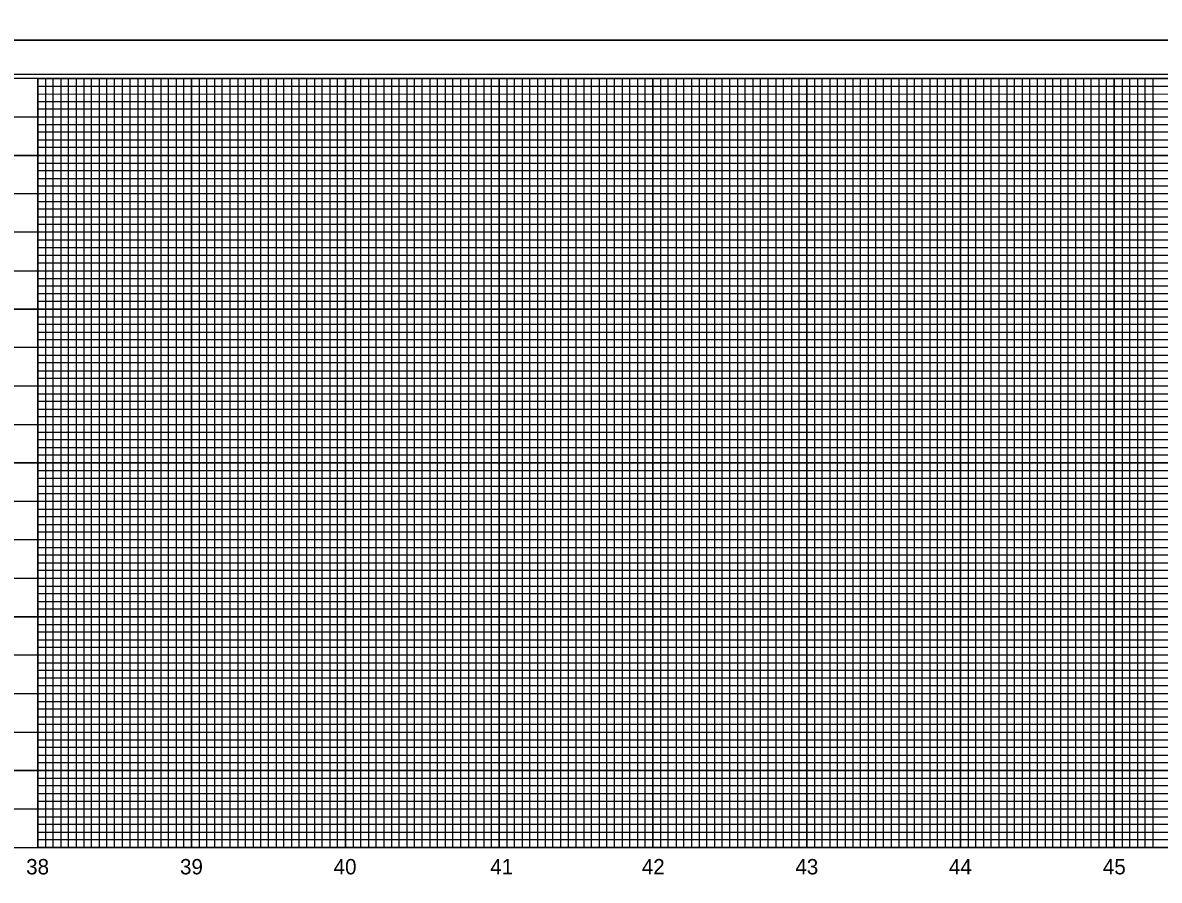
# Model space of a CAD drawing. Extents: x 1754992 to 1757273, y 732111 to 735411.
# Drawn here: x 1755388 to 1756127, y 733764 to 734322 of the extents above; entities that cross this region are included whole.
import ezdxf

# ---------------------------------------------------------------- set-up
doc = ezdxf.new("R2010")
doc.units = 0
for name, color, linetype in [('Scratch_Level_3', 7, 'Continuous'), ('Sheet Cutting Line CELL', 7, 'Continuous'), ('Sheet DOT Grid CELL', 7, 'Continuous'), ('Sheet Plot Border Inside CELL', 7, 'Continuous'), ('Sheet Plot Border Outside CELL', 7, 'Continuous'), ('Sheet Profile CELL', 7, 'Continuous'), ('Sheet Profile Grid Major CELL', 7, 'Continuous'), ('Sheet Profile Grid Middle CELL', 7, 'Continuous'), ('Sheet Profile Grid Minor CELL', 7, 'Continuous')]:
    doc.layers.add(name, color=color, linetype=linetype)

msp = doc.modelspace()

# ---------------------------------------------------------------- linework, layer by layer
at = {"layer": 'Scratch_Level_3'}
msp.add_lwpolyline([(1755397.67, 733785.78), (1755397.67, 734285.78), (1756647.62, 734285.78), (1756647.63, 734052.66), (1756647.67, 733785.78)], close=True, dxfattribs=at)
at = {"layer": 'Sheet Cutting Line CELL'}
for p, q in [((1755180.67, 734310.78), (1756864.67, 734310.78)), ((1756864.67, 734310.78), (1755180.67, 734310.78))]:
    msp.add_line(p, q, dxfattribs=at)
at = {"layer": 'Sheet DOT Grid CELL'}
for p, q in [((1755397.67, 733785.78), (1755397.67, 734285.78)), ((1755447.67, 733785.78), (1755447.67, 734285.78)), ((1755497.67, 733785.78), (1755497.67, 734285.78)), ((1755547.67, 733785.78), (1755547.67, 734285.78)), ((1755597.67, 733785.78), (1755597.67, 734285.78)), ((1755647.67, 733785.78), (1755647.67, 734285.78)), ((1755697.67, 733785.78), (1755697.67, 734285.78)), ((1755747.67, 733785.78), (1755747.67, 734285.78)), ((1755797.67, 733785.78), (1755797.67, 734285.78)), ((1755847.67, 733785.78), (1755847.67, 734285.78)), ((1755897.67, 733785.78), (1755897.67, 734285.78)), ((1755947.67, 733785.78), (1755947.67, 734285.78)), ((1755997.67, 733785.78), (1755997.67, 734285.78)), ((1756047.67, 733785.78), (1756047.67, 734285.78)), ((1756097.67, 733785.78), (1756097.67, 734285.78)), ((1756647.62, 734235.78), (1755347.67, 734235.78)), ((1756647.62, 734185.78), (1755347.67, 734185.78)), ((1756647.67, 734135.78), (1755347.67, 734135.78)), ((1756647.63, 734085.78), (1755347.67, 734085.78)), ((1756847.67, 734035.78), (1755347.67, 734035.78)), ((1756847.67, 733985.78), (1755347.67, 733985.78)), ((1756847.67, 733935.78), (1755347.67, 733935.78)), ((1756847.67, 733885.78), (1755347.67, 733885.78)), ((1756847.67, 733835.78), (1755347.67, 733835.78))]:
    msp.add_line(p, q, dxfattribs=at)
at = {"layer": 'Sheet Plot Border Inside CELL'}
msp.add_lwpolyline([(1755193.67, 733233.23), (1756860.17, 733233.23), (1756860.17, 734288.33), (1755193.67, 734288.33)], close=True, dxfattribs=at)
at = {"layer": 'Sheet Plot Border Outside CELL'}
for points in [[(1755180.67, 734310.78), (1756864.67, 734310.78), (1756864.67, 735410.78), (1755180.67, 735410.78)], [(1755180.67, 733210.78), (1756864.67, 733210.78), (1756864.67, 734310.78), (1755180.67, 734310.78)]]:
    msp.add_lwpolyline(points, close=True, dxfattribs=at)
at = {"layer": 'Sheet Profile CELL'}
msp.add_line((1755347.67, 733785.78), (1756847.67, 733785.78), dxfattribs=at)
msp.add_lwpolyline([(1756847.67, 734285.78), (1755347.67, 734285.78), (1755347.67, 733235.78), (1756847.67, 733235.78)], close=True, dxfattribs=at)
at = {"layer": 'Sheet Profile Grid Major CELL'}
for points in [[(1755397.67, 734285.78), (1755397.67, 733785.78), (1755447.67, 733785.78), (1755447.67, 734285.78), (1755497.67, 734285.78), (1755497.67, 733785.78), (1755547.67, 733785.78), (1755547.67, 734285.78), (1755597.67, 734285.78), (1755597.67, 733785.78), (1755647.67, 733785.78), (1755647.67, 734285.78), (1755697.67, 734285.78), (1755697.67, 733785.78), (1755747.67, 733785.78), (1755747.67, 734285.78), (1755797.67, 734285.78), (1755797.67, 733785.78), (1755847.67, 733785.78), (1755847.67, 734285.78), (1755897.67, 734285.78), (1755897.67, 733785.78), (1755947.67, 733785.78), (1755947.67, 734285.78), (1755997.67, 734285.78), (1755997.67, 733785.78), (1756047.67, 733785.78), (1756047.67, 734285.78), (1756097.67, 734285.78), (1756097.67, 733785.78), (1756147.67, 733785.78)], [(1755347.67, 734235.78), (1756647.67, 734235.78)], [(1756647.67, 734185.78), (1755347.67, 734185.78), (1755347.67, 734135.78), (1756647.67, 734135.78)], [(1756647.63, 734085.78), (1755347.67, 734085.78), (1755347.67, 734035.78), (1756847.67, 734035.78)], [(1756847.67, 733985.78), (1755347.67, 733985.78), (1755347.67, 733935.78), (1756847.67, 733935.78)], [(1756847.67, 733885.78), (1755347.67, 733885.78), (1755347.67, 733885.78), (1755347.67, 733835.78), (1756847.67, 733835.78)]]:
    msp.add_lwpolyline(points, dxfattribs=at)
at = {"layer": 'Sheet Profile Grid Middle CELL'}
msp.add_line((1755347.67, 734260.78), (1756647.62, 734260.78), dxfattribs=at)
for points in [[(1755422.67, 734285.78), (1755422.67, 733785.78), (1755472.67, 733785.78), (1755472.67, 734285.78), (1755522.67, 734285.78), (1755522.67, 733785.78), (1755572.67, 733785.78), (1755572.67, 734285.78), (1755622.67, 734285.78), (1755622.67, 733785.78), (1755672.67, 733785.78), (1755672.67, 734285.78), (1755722.67, 734285.78), (1755722.67, 733785.78), (1755772.67, 733785.78), (1755772.67, 734285.78), (1755822.67, 734285.78), (1755822.67, 733785.78), (1755872.67, 733785.78), (1755872.67, 734285.78), (1755922.67, 734285.78), (1755922.67, 733785.78), (1755972.67, 733785.78), (1755972.67, 733785.78), (1755972.67, 734285.78), (1756022.67, 734285.78), (1756022.67, 733785.78), (1756072.67, 733785.78), (1756072.67, 734285.78), (1756122.67, 734285.78), (1756122.67, 733785.78), (1756172.67, 733785.78)], [(1756647.67, 734210.78), (1755347.67, 734210.78), (1755347.67, 734160.78), (1756647.67, 734160.78)], [(1756647.62, 734110.78), (1755347.67, 734110.78), (1755347.67, 734060.78), (1756647.63, 734060.78)], [(1756847.67, 734010.78), (1755347.67, 734010.78), (1755347.67, 733960.78), (1756847.67, 733960.78)], [(1756847.67, 733910.78), (1755347.67, 733910.78), (1755347.67, 733860.78), (1756847.67, 733860.78)], [(1756847.67, 733810.78), (1755347.67, 733810.78)]]:
    msp.add_lwpolyline(points, dxfattribs=at)
at = {"layer": 'Sheet Profile Grid Minor CELL'}
for p, q in [((1755397.67, 734280.78), (1756647.67, 734280.78)), ((1755397.67, 734275.78), (1755397.67, 734275.78)), ((1756647.67, 734275.78), (1755397.67, 734275.43)), ((1755397.67, 734270.78), (1756647.67, 734270.78)), ((1756647.62, 734150.78), (1755397.67, 734150.78)), ((1756647.67, 734145.78), (1755397.67, 734145.78)), ((1756647.67, 734140.78), (1755397.67, 734140.78)), ((1755397.67, 734130.78), (1756647.67, 734130.78)), ((1756647.67, 734125.78), (1755397.67, 734125.78)), ((1755397.67, 734120.78), (1756647.62, 734120.78)), ((1756647.62, 734100.78), (1755397.67, 734100.78)), ((1755397.67, 734095.78), (1756647.62, 734095.78)), ((1756647.63, 734075.78), (1755397.67, 734075.78)), ((1755397.67, 734070.78), (1756647.63, 734070.78)), ((1756797.67, 734050.78), (1755397.67, 734050.78)), ((1755397.67, 734045.78), (1756797.67, 734045.78)), ((1756797.67, 734040.78), (1755397.67, 734040.78)), ((1755397.67, 734030.78), (1756797.67, 734030.78)), ((1756797.67, 734025.78), (1755397.67, 734025.78)), ((1755397.67, 734020.78), (1756797.67, 734020.78)), ((1756797.67, 734015.78), (1755397.67, 734015.78)), ((1755397.67, 734005.78), (1756797.67, 734005.78)), ((1756797.67, 734000.78), (1755397.67, 734000.78)), ((1755397.67, 733995.78), (1756797.67, 733995.78)), ((1756797.67, 733990.78), (1755397.67, 733990.78)), ((1755397.67, 733980.78), (1756797.67, 733980.78)), ((1756797.67, 733975.78), (1755397.67, 733975.78)), ((1755397.67, 733970.78), (1756797.67, 733970.78)), ((1756797.67, 733965.78), (1755397.67, 733965.78)), ((1755397.67, 733955.78), (1756797.67, 733955.78)), ((1756797.67, 733950.78), (1755397.67, 733950.78)), ((1755397.67, 733945.78), (1756797.67, 733945.78)), ((1756797.67, 733940.78), (1755397.67, 733940.78)), ((1755397.67, 733930.78), (1756797.67, 733930.78)), ((1756797.67, 733925.78), (1755397.67, 733925.78)), ((1755397.67, 733920.78), (1756797.67, 733920.78)), ((1756797.67, 733915.78), (1755397.67, 733915.78)), ((1755397.67, 733905.78), (1756797.67, 733905.78)), ((1756797.67, 733900.78), (1755397.67, 733900.78)), ((1756797.67, 733895.78), (1755397.67, 733895.78)), ((1756797.67, 733890.78), (1755397.67, 733890.78)), ((1755397.67, 733880.78), (1756797.67, 733880.78)), ((1756797.67, 733875.78), (1755397.67, 733875.78)), ((1755397.67, 733870.78), (1756797.67, 733870.78)), ((1756797.67, 733865.78), (1755397.67, 733865.78)), ((1755397.67, 733855.78), (1756797.67, 733855.78)), ((1756797.67, 733850.78), (1755397.67, 733850.78)), ((1755397.67, 733845.78), (1756797.67, 733845.78)), ((1756797.67, 733840.78), (1755397.67, 733840.78)), ((1755397.67, 733830.78), (1756797.67, 733830.78)), ((1756797.67, 733825.78), (1755397.67, 733825.78)), ((1755397.67, 733820.78), (1756797.67, 733820.78)), ((1756797.67, 733815.78), (1755397.67, 733815.78)), ((1755397.67, 733805.78), (1756797.67, 733805.78)), ((1756797.67, 733800.78), (1755397.67, 733800.78)), ((1755397.67, 733795.78), (1756797.67, 733795.78))]:
    msp.add_line(p, q, dxfattribs=at)
for points in [[(1755402.67, 734285.78), (1755402.67, 733785.78), (1755407.67, 733785.78), (1755407.67, 734285.78), (1755412.67, 734285.78), (1755412.67, 733785.78), (1755417.67, 733785.78), (1755417.67, 734285.78), (1755427.67, 734285.78), (1755427.67, 733785.78), (1755432.67, 733785.78), (1755432.67, 734285.78), (1755437.67, 734285.78), (1755437.67, 733785.78), (1755442.67, 733785.78), (1755452.67, 733785.78), (1755457.67, 733785.78), (1755457.67, 734285.78), (1755462.67, 734285.78), (1755462.67, 733785.78), (1755467.67, 733785.78), (1755467.67, 734285.78), (1755477.67, 734285.78), (1755477.67, 733785.78), (1755482.67, 733785.78), (1755482.67, 734285.78), (1755487.67, 734285.78), (1755487.67, 733785.78), (1755492.67, 733785.78), (1755492.67, 734285.78), (1755502.67, 734285.78), (1755502.67, 733785.78), (1755507.67, 733785.78), (1755507.67, 734285.78), (1755512.67, 734285.78), (1755512.67, 733785.78), (1755517.67, 733785.78), (1755517.67, 734285.78), (1755527.67, 734285.78), (1755527.67, 733785.78), (1755532.67, 733785.78), (1755532.67, 734285.78), (1755537.67, 734285.78), (1755537.67, 733785.78), (1755542.67, 733785.78), (1755542.67, 734285.78), (1755552.67, 734285.78), (1755552.67, 733785.78), (1755557.67, 733785.78), (1755557.67, 734285.78), (1755562.67, 734285.78), (1755562.67, 733785.78), (1755567.67, 733785.78), (1755567.67, 734285.78), (1755577.67, 734285.78), (1755577.67, 733785.78), (1755582.67, 733785.78), (1755582.67, 734285.78), (1755587.67, 734285.78), (1755587.67, 733785.78), (1755592.67, 733785.78), (1755592.67, 734285.78), (1755602.67, 734285.78), (1755602.67, 733785.78), (1755607.67, 733785.78), (1755607.67, 734285.78), (1755612.67, 734285.78), (1755612.67, 733785.78)], [(1755442.67, 733785.78), (1755442.67, 734285.78), (1755452.67, 734285.78), (1755452.67, 733785.78)], [(1755612.67, 733785.78), (1755617.67, 733785.78), (1755617.67, 734285.78), (1755627.67, 734285.78), (1755627.67, 733785.78), (1755632.67, 733785.78), (1755632.67, 734285.78), (1755637.67, 734285.78), (1755637.67, 733785.78), (1755642.67, 733785.78), (1755642.67, 734285.78), (1755652.67, 734285.78), (1755652.67, 733785.78), (1755657.67, 733785.78), (1755657.67, 734285.78), (1755662.67, 734285.78), (1755662.67, 733785.78), (1755667.67, 733785.78), (1755667.67, 734285.78), (1755677.67, 734285.78), (1755677.67, 733785.78), (1755682.67, 733785.78), (1755682.67, 734285.78), (1755687.67, 734285.78), (1755687.67, 733785.78), (1755692.67, 733785.78), (1755692.67, 734285.78), (1755702.67, 734285.78), (1755702.67, 733785.78), (1755707.67, 733785.78), (1755707.67, 734285.78), (1755712.67, 734285.78), (1755712.67, 733785.78), (1755717.67, 733785.78), (1755717.67, 734285.78), (1755727.67, 734285.78), (1755727.67, 733785.78), (1755732.67, 733785.78), (1755732.67, 734285.78), (1755737.67, 734285.78), (1755737.67, 733785.78), (1755742.67, 733785.78), (1755742.67, 734285.78), (1755752.67, 734285.78), (1755752.67, 733785.78), (1755757.67, 733785.78), (1755757.67, 734285.78), (1755762.67, 734285.78), (1755762.67, 733785.78), (1755767.67, 733785.78), (1755767.67, 734285.78), (1755777.67, 734285.78), (1755777.67, 733785.78), (1755782.67, 733785.78), (1755782.67, 734285.78), (1755787.67, 734285.78), (1755787.67, 733785.78), (1755792.67, 733785.78), (1755792.67, 734285.78), (1755802.67, 734285.78), (1755802.67, 733785.78), (1755807.67, 733785.78), (1755807.67, 734285.78), (1755812.67, 734285.78), (1755812.67, 733785.78), (1755817.67, 733785.78), (1755817.67, 734285.78), (1755827.67, 734285.78), (1755827.67, 733785.78), (1755832.67, 733785.78), (1755832.67, 734285.78), (1755837.67, 734285.78), (1755837.67, 733785.78), (1755842.67, 733785.78), (1755842.67, 734285.78), (1755852.67, 734285.78), (1755852.67, 733785.78), (1755857.67, 733785.78), (1755857.67, 734285.78), (1755862.67, 734285.78), (1755862.67, 733785.78), (1755867.67, 733785.78), (1755867.67, 734285.78), (1755877.67, 734285.78), (1755877.67, 733785.78), (1755882.67, 733785.78), (1755882.67, 734285.78), (1755887.67, 734285.78), (1755887.67, 733785.78), (1755892.67, 733785.78), (1755892.67, 734285.78), (1755902.67, 734285.78), (1755902.67, 733785.78), (1755907.67, 733785.78), (1755907.67, 734285.78), (1755912.67, 734285.78), (1755912.67, 733785.78), (1755917.67, 733785.78), (1755917.67, 734285.78), (1755927.67, 734285.78)], [(1755927.67, 734285.78), (1755927.67, 733785.78), (1755932.67, 733785.78), (1755932.67, 734285.78), (1755937.67, 734285.78), (1755937.67, 733785.78), (1755942.67, 733785.78), (1755942.67, 734285.78), (1755952.67, 734285.78), (1755952.67, 733785.78), (1755957.67, 733785.78), (1755957.67, 734285.78), (1755962.67, 734285.78), (1755962.67, 733785.78), (1755967.67, 733785.78), (1755967.67, 734285.78), (1755977.67, 734285.78), (1755977.67, 733785.78), (1755982.67, 733785.78), (1755982.67, 734285.78), (1755987.67, 734285.78), (1755987.67, 733785.78), (1755992.67, 733785.78), (1755992.67, 734285.78), (1756002.67, 734285.78), (1756002.67, 733785.78), (1756007.67, 733785.78), (1756007.67, 734285.78), (1756012.67, 734285.78), (1756012.67, 733785.78), (1756017.67, 733785.78), (1756017.67, 734285.78), (1756027.67, 734285.78), (1756027.67, 733785.78), (1756032.67, 733785.78), (1756032.67, 734285.78), (1756037.67, 734285.78), (1756037.67, 733785.78), (1756042.67, 733785.78), (1756042.67, 734285.78), (1756052.67, 734285.78), (1756052.67, 733785.78), (1756052.67, 733785.78), (1756057.67, 733785.78), (1756057.67, 734285.78), (1756062.67, 734285.78), (1756062.67, 733785.78), (1756067.67, 733785.78), (1756067.67, 734285.78), (1756077.67, 734285.78), (1756077.67, 733785.78), (1756082.67, 733785.78), (1756082.67, 734285.78), (1756087.67, 734285.78), (1756087.67, 733785.78), (1756092.67, 733785.78), (1756092.67, 734285.78), (1756102.67, 734285.78), (1756102.67, 733785.78), (1756107.67, 733785.78), (1756107.67, 734285.78), (1756112.67, 734285.78), (1756112.67, 733785.78), (1756117.67, 733785.78), (1756117.67, 734285.78), (1756127.67, 734285.78)], [(1756647.67, 734265.78), (1755397.67, 734265.78), (1755397.67, 734255.78), (1756647.67, 734255.78)], [(1756647.62, 734250.78), (1755397.67, 734250.78), (1755397.67, 734245.78), (1756647.67, 734245.78)], [(1756647.67, 734240.78), (1755397.67, 734240.78), (1755397.67, 734230.78), (1756647.67, 734230.78)], [(1756647.67, 734225.78), (1755397.67, 734225.78), (1755397.67, 734220.78), (1756647.67, 734220.78)], [(1756647.67, 734215.78), (1755397.67, 734215.78), (1755397.67, 734205.78), (1756647.67, 734205.78)], [(1756647.67, 734200.78), (1755397.67, 734200.78), (1755397.67, 734195.78), (1756647.67, 734195.78)], [(1756647.67, 734190.78), (1755397.67, 734190.78), (1755397.67, 734180.78), (1756647.67, 734180.78)], [(1756647.67, 734175.68), (1755397.77, 734175.68), (1755397.77, 734170.78), (1756647.67, 734170.78)], [(1756647.67, 734165.78), (1755397.67, 734165.78), (1755397.67, 734155.78), (1756647.67, 734155.78)], [(1756647.62, 734115.78), (1755397.67, 734115.78), (1755397.67, 734105.78), (1756647.62, 734105.78)], [(1756647.62, 734090.78), (1755397.67, 734090.78), (1755397.67, 734080.78), (1756647.63, 734080.78)], [(1756647.63, 734065.78), (1755397.67, 734065.78), (1755397.67, 734055.78), (1756647.63, 734055.78)], [(1756797.67, 733790.78), (1755397.67, 733790.78)]]:
    msp.add_lwpolyline(points, dxfattribs=at)

# ---------------------------------------------------------------- texts
at = {"layer": 'Scratch_Level_3'}
for s, p in [('38', (1755390.14, 733768.28)), ('39', (1755490.18, 733768.28)), ('40', (1755590.06, 733768.28)), ('41', (1755691.89, 733768.28)), ('42', (1755790.44, 733768.28)), ('43', (1755890.28, 733768.28)), ('44', (1755990.12, 733768.28)), ('45', (1756090.21, 733768.28))]:
    msp.add_text(s, height=10, dxfattribs=at).set_placement(p)

doc.saveas('drawing.dxf')
